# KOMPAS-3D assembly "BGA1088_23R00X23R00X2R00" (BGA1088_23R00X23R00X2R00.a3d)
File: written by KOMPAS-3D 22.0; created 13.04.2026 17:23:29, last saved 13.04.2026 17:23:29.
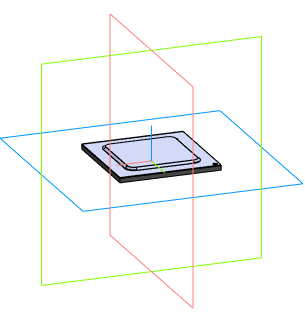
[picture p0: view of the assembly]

Document properties: Автор: Andrey; Полное имя файла: C:\Users\User1\Documents\BGA1088_23R00X23R00X2R00.a3d

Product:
- Component [assembly]: RK3588  | qty 1  | source file: RK3588.a3d
- Part/product: BGA1088_23R00X23R00X2R00
    Комментарий: BGA1088_23R00X23R00X2R00

Referenced files in C:\Users\User1\Documents\: RK3588.a3d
